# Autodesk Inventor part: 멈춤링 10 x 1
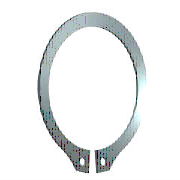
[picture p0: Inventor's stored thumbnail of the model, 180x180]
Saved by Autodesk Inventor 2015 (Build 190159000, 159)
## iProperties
IsCustomPart: 0
Company: 한국ATC센터
Created: 2014-07
Part Number: 멈춤링 10 x 1
Material: Steel, Mild
Description: 리테이닝 링(C형)
Document SubType Name: Modeling
Standard: KS B 1336
Designer: KYOUNG IL JANG
Standards Organization: KS
Language: ko-KR
Size Designation: 10 x 1
Categories: <MemberInstance><Categories><Category DisplayName="샤프트 부품" InternalName="7f7aeb1f-a693-4053-b835-cee3144e0d98" Mnemonic="SHFT"><Category DisplayName="써클립" Inter
Density: 7.85 g/cm^3
Appearance: Steel
Mass: 0.422549 g
Surface Area: 1.9243 cm^2
Volume: 0.0538279 cm^3
Author: KYOUNG IL JANG
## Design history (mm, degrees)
sketch "스케치1"
  geometry: L1 (-6, 0)-(6, 0) reference; L2 (0, 20.189)-(0, -80.536) reference; L3 (-48.09, 0)-(48.09, 0) reference; L4 (-0.3, -9.791)-(-0.3, -12.791); L5 (-0.3, -6.54)-(-0.3, -13.29); L6 (-2.795, 1.6)-(3.672, 1.6); L7 (0.3, -6.54)-(0.3, -13.29); L8 (0.3, -9.791)-(0.3, -12.791); C1 r 0.6 at (-1.2, -11.486); C2 r 0.6 at (1.2, -11.486); A1 r 4.8 centre (0, -5) between (0.3, -9.791) and (-0.3, -9.791); A2 r 6.2 centre (0, -4.6) between (2.988, -10.033) and (-2.988, -10.033); A3 r 7.796 centre (0, -5) between (-1.418, -12.666) and (-0.3, -12.791); A4 r 1.2 centre (-1.2, -11.486) between (-2.383, -11.285) and (-1.418, -12.666); A5 r 1.2 centre (-3.566, -11.084) between (-2.383, -11.285) and (-2.988, -10.033); A6 r 1.2 centre (3.566, -11.084) between (2.988, -10.033) and (2.383, -11.285); A7 r 1.2 centre (1.2, -11.486) between (1.418, -12.666) and (2.383, -11.285); A8 r 7.796 centre (0, -5) between (0.3, -12.791) and (1.418, -12.666)
  constraints: 16 point on circle, 12 end point, 10 centre point, 9 symmetric about line, 5 point on line, 4 tangent, 3 coincident, 2 horizontal, 1 perpendicular, 1 vertical, 5 other
  dimensions: "d0" = 9.6 diameter of A1 (= ND); "d1" = 3 distance of L4.end L4.start (= SRB2); "d6" = 0.3 distance between parallel lines of L2 L5 (= 0.25 x SD5); "d7" = 1.6 distance between parallel lines of L6 L3 (= SRB1); "d8" = 0.4 distance of A1.centre A2.centre (= 0.25 x SRB1); "d9" = 1.2 radius of A4 (= SD5); "d10" = 1.2 radius of A5 (= SD5); "d11" = 0.9 distance from line of L4 A4.centre (= 0.75 x SD5); "d12" = 1.2 diameter of C1 (= SD5); "d13" = 1.2 diameter of C2 (= SD5); "d14" = 5 distance from line of A1.centre L1 (= 0.5 x WD)
extrude "본체" new body sketch "스케치1" distance "d2" = 1 (= SD); taper "d3" = 0 deg
workaxis "Work Axis1"
workplane "Work Plane1"
body "Solid1"
other parameters: "SD" = 1 [user parameter; used in 1 equation term], "SRB1" = 1.6 [user parameter; used in 2 equation terms], "ND" = 9.6 [user parameter; used in 1 equation term], "SRB2" = 3 [user parameter; used in 1 equation term], "SD5" = 1.2 [user parameter; used in 6 equation terms], "d15" = 0, "d16" = 0, "d17" = 0, "d41" = 0, "d42" = 0, "SD3" = 9.3 [user parameter], "WDMAX" = 11 [user parameter]
